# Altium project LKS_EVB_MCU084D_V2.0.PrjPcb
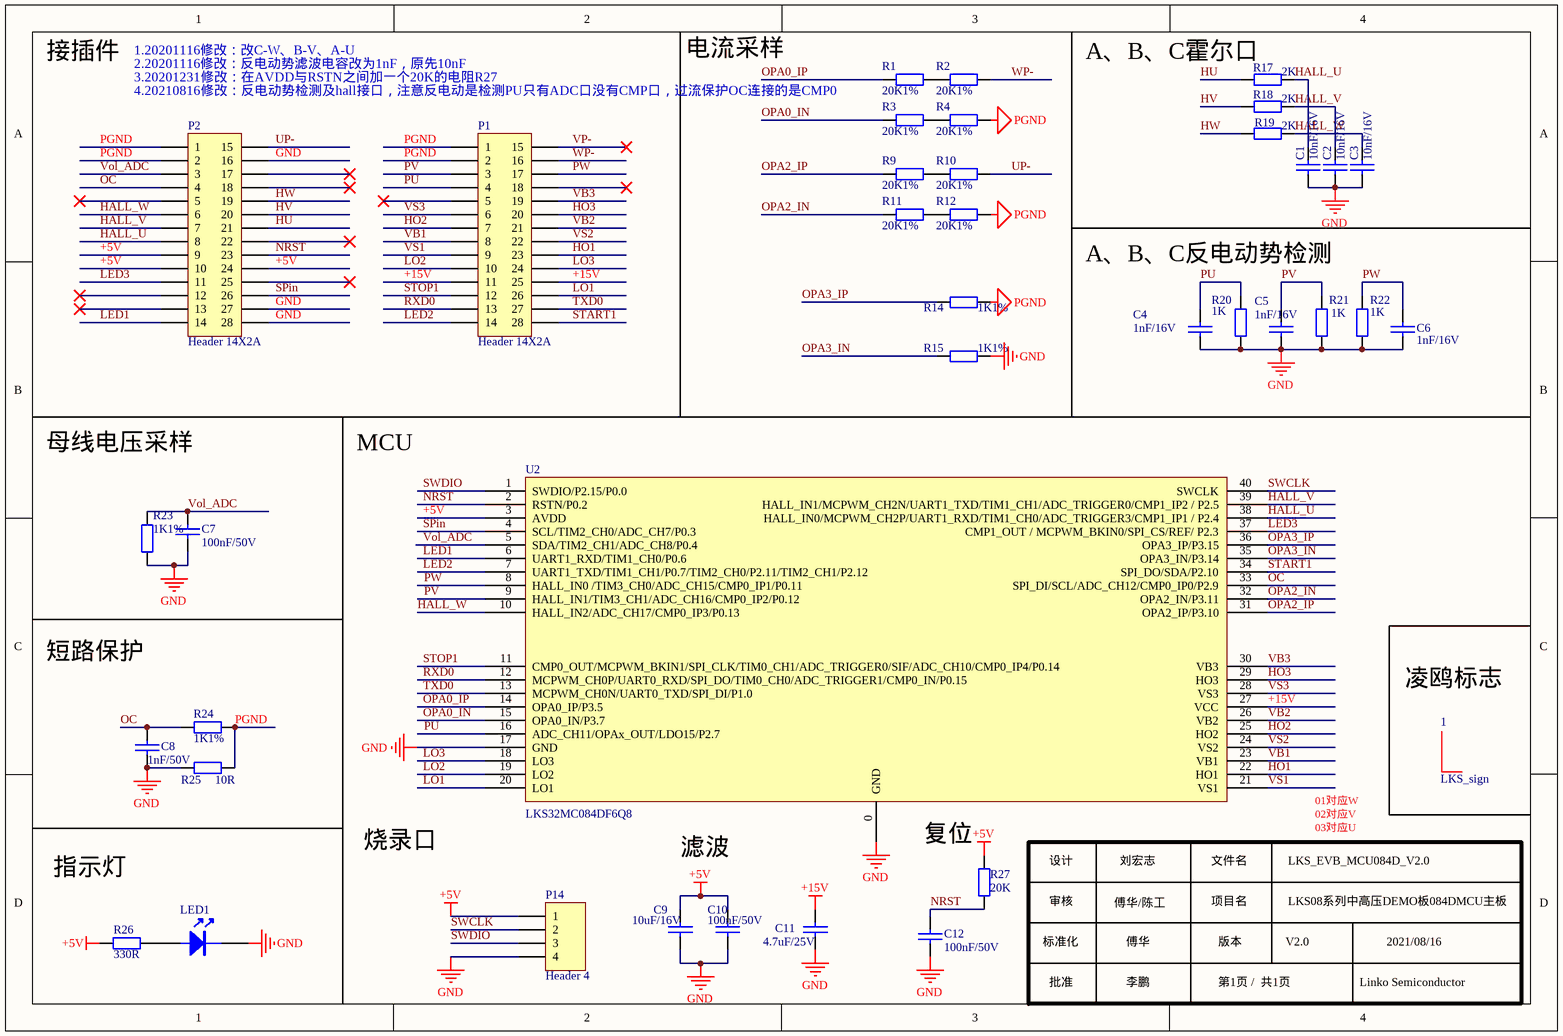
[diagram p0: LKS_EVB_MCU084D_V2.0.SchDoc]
1 sheet, 39 parts. Net scope: global (net labels, ports and power ports of the same name join across sheets).
Board file: LKS_EVB_MCU084D_V2.0.PcbDoc

## Sheet LKS_EVB_MCU084D_V2.0.SchDoc
size A4; SheetNumber: 1; SheetTotal: 1

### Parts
1  LKS_sign  [LKS_LOGO2]
C1  10nF/16V  [0603C]
C2  10nF/16V  [0603C]
C3  10nF/16V  [0603C]
C4  1nF/16V  [0603C]
C5  1nF/16V  [0603C]
C6  1nF/16V  [0603C]
C7  100nF/50V  [0603C]
C8  1nF/50V  [0603C]
C9  10uF/16V  [0603C]
C10  100nF/50V  [0603C]
C11  4.7uF/25V  [0603C]
C12  100nF/50V  [0603C]
LED1  LED  [LED 0603R]  (value not drawn)
P1  Header 14X2A  [HDR2X14_CEN]
P2  Header 14X2A  [HDR2X14_CEN]
P14  Header 4  [HDR1X4]
R1  20K1%  [0603R]
R2  20K1%  [0603R]
R3  20K1%  [0603R]
R4  20K1%  [0603R]
R9  20K1%  [0603R]
R10  20K1%  [0603R]
R11  20K1%  [0603R]
R12  20K1%  [0603R]
R14  1K1%  [0603R]
R15  1K1%  [0603R]
R17  2K  [0603R]
R18  2K  [0603R]
R19  2K  [0603R]
R20  1K  [0603R]
R21  1K  [0603R]
R22  1K  [0603R]
R23  1K1%  [0603R]
R24  1K1%  [0603R]
R25  10R  [0603R]
R26  330R  [0603R]
R27  20K  [0603R]
U2  LKS32MC084DF6Q8  [QFN40]

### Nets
+5V: C9.2 C10.2 P2.9 P2.10 P2.24 P14.1 R26.2 R27.2 U2.3(AVDD)
+15V: C11.2 P1.11 P1.25 U2.27(VCC)
GND: C1.2 C2.2 C3.2 C4.2 C5.2 C6.2 C7.1 C8.1 C9.1 C10.1 C11.1 C12.2 LED1.2(K) P2.16 P2.27 P2.28 P14.4 R15.1 R20.2 R21.2 R22.2 R23.1 R25.2 U2.0(GND) U2.17(GND)
PGND: P1.1 P1.2 P2.1 P2.2 R4.1 R12.1 R14.1 R24.2 R25.1
HALL_U: C1.1 P2.8 R17.2 U2.38(HALL_IN0/MCPWM_CH2P/UART1_RXD/TIM1_CH0/ADC_TRIGGER3/CMP1_IP1_/_P2.4)
HALL_V: C2.1 P2.7 R18.2 U2.39(HALL_IN1/MCPWM_CH2N/UART1_TXD/TIM1_CH1/ADC_TRIGGER0/CMP1_IP2_/_P2.5)
HALL_W: C3.1 P2.6 R19.2 U2.10(HALL_IN2/ADC_CH17/CMP0_IP3/P0.13)
HO1: P1.23 U2.22(HO1)
HO2: P1.7 U2.25(HO2)
HO3: P1.20 U2.29(HO3)
HU: P2.21 R17.1
HV: P2.20 R18.1
HW: P2.19 R19.1
LED1: P2.14 U2.6(UART1_RXD/TIM1_CH0/P0.6)
LED2: P1.14 U2.7(UART1_TXD/TIM1_CH1/P0.7/TIM2_CH0/P2.11/TIM2_CH1/P2.12)
LED3: P2.11 U2.37(CMP1_OUT_/_MCPWM_BKIN0/SPI_CS/REF/_P2.3)
LO1: P1.26 U2.20(LO1)
LO2: P1.10 U2.19(LO2)
LO3: P1.24 U2.18(LO3)
NRST: C12.1 P2.23 R27.1 U2.2(RSTN/P0.2)
OC: C8.2 P2.4 R24.1 U2.33(SPI_DI/SCL/ADC_CH12/CMP0_IP0/P2.9)
OPA0_IN: R3.2 U2.15(OPA0_IN/P3.7)
OPA0_IP: R1.2 U2.14(OPA0_IP/P3.5)
OPA2_IN: R11.2 U2.32(OPA2_IN/P3.11)
OPA2_IP: R9.2 U2.31(OPA2_IP/P3.10)
OPA3_IN: R15.2 U2.35(OPA3_IN/P3.14)
OPA3_IP: R14.2 U2.36(OPA3_IP/P3.15)
PU: C4.1 P1.4 R20.1 U2.16(ADC_CH11/OPAx_OUT/LDO15/P2.7)
PV: C5.1 P1.3 R21.1 U2.9(HALL_IN1/TIM3_CH1/ADC_CH16/CMP0_IP2/P0.12)
PW: C6.1 P1.17 R22.1 U2.8(HALL_IN0_/TIM3_CH0/ADC_CH15/CMP0_IP1/P0.11)
RXD0: P1.13 U2.12(MCPWM_CH0P/UART0_RXD/SPI_DO/TIM0_CH0/ADC_TRIGGER1/CMP0_IN/P0.15)
SPin: P2.26 U2.4(SCL/TIM2_CH0/ADC_CH7/P0.3)
START1: P1.28 U2.34(SPI_DO/SDA/P2.10)
STOP1: P1.12 U2.11(CMP0_OUT/MCPWM_BKIN1/SPI_CLK/TIM0_CH1/ADC_TRIGGER0/SIF/ADC_CH10/CMP0_IP4/P0.14)
SWCLK: P14.2 U2.40(SWCLK)
SWDIO: P14.3 U2.1(SWDIO/P2.15/P0.0)
TXD0: P1.27 U2.13(MCPWM_CH0N/UART0_TXD/SPI_DI/P1.0)
UP-: P2.15 R10.1
VB1: P1.8 U2.23(VB1)
VB2: P1.21 U2.26(VB2)
VB3: P1.19 U2.30(VB3)
Vol_ADC: C7.2 P2.3 R23.2 U2.5(SDA/TIM2_CH1/ADC_CH8/P0.4)
VP-: P1.15
VS1: P1.9 U2.21(VS1)
VS2: P1.22 U2.24(VS2)
VS3: P1.6 U2.28(VS3)
WP-: P1.16 R2.1
NetLED1_1: LED1.1(A) R26.1
NetR1_1: R1.1 R2.2
NetR3_1: R3.1 R4.2
NetR9_1: R9.1 R10.2
NetR11_1: R11.1 R12.2

Not connected (* = marked no-connect by the designer): P1 5* 18*; P2 5* 12* 13* 17* 18* 22* 25*

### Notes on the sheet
- 接插件
- 1.20201116修改：改C-W、B-V、A-U
- 2.20201116修改：反电动势滤波电容改为1nF，原先10nF
- 3.20201231修改：在AVDD与RSTN之间加一个20K的电阻R27
- 4.20210816修改：反电动势检测及hall接口，注意反电动是检测PU只有ADC口没有CMP口，过流保护OC连接的是CMP0
- 母线电压采样
- 短路保护
- (near 1) 凌鸥标志
- 烧录口
- (near U2) 复位
- 01对应W
- 02对应V
- 03对应U
- 指示灯
- (near U2) 滤波
- 设计
- 审核
- 傅华/陈工
- 刘宏志
- 文件名
- 项目名
- LKS_EVB_MCU084D_V2.0
- LKS08系列中高压DEMO板084DMCU主板
- 标准化
- 批准
- 傅华
- 李鹏
- 版本
- 第1页 /  共1页
- V2.0
- Linko Semiconductor
- 2021/08/16
- Labels drawn without touching a wire or pin: A、B、C反电动势检测, A、B、C霍尔口, MCU, 电流采样

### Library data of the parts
C1-C6 = CAP: Capacitor
C7-C12 = C: Capacitor
LED1 = LED: LED_Light
P1 P2 = Header 14X2A: Header, 14-Pin, Dual row
P14 = Header 4: Header, 4-Pin
R1-R4 R9-R12 R14 R15 R17-R25 R27 = Res: Resistor; Value: K
R26 = Res: Resistor; Value: 330
U2 = LKS084DF6Q8: 芯片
